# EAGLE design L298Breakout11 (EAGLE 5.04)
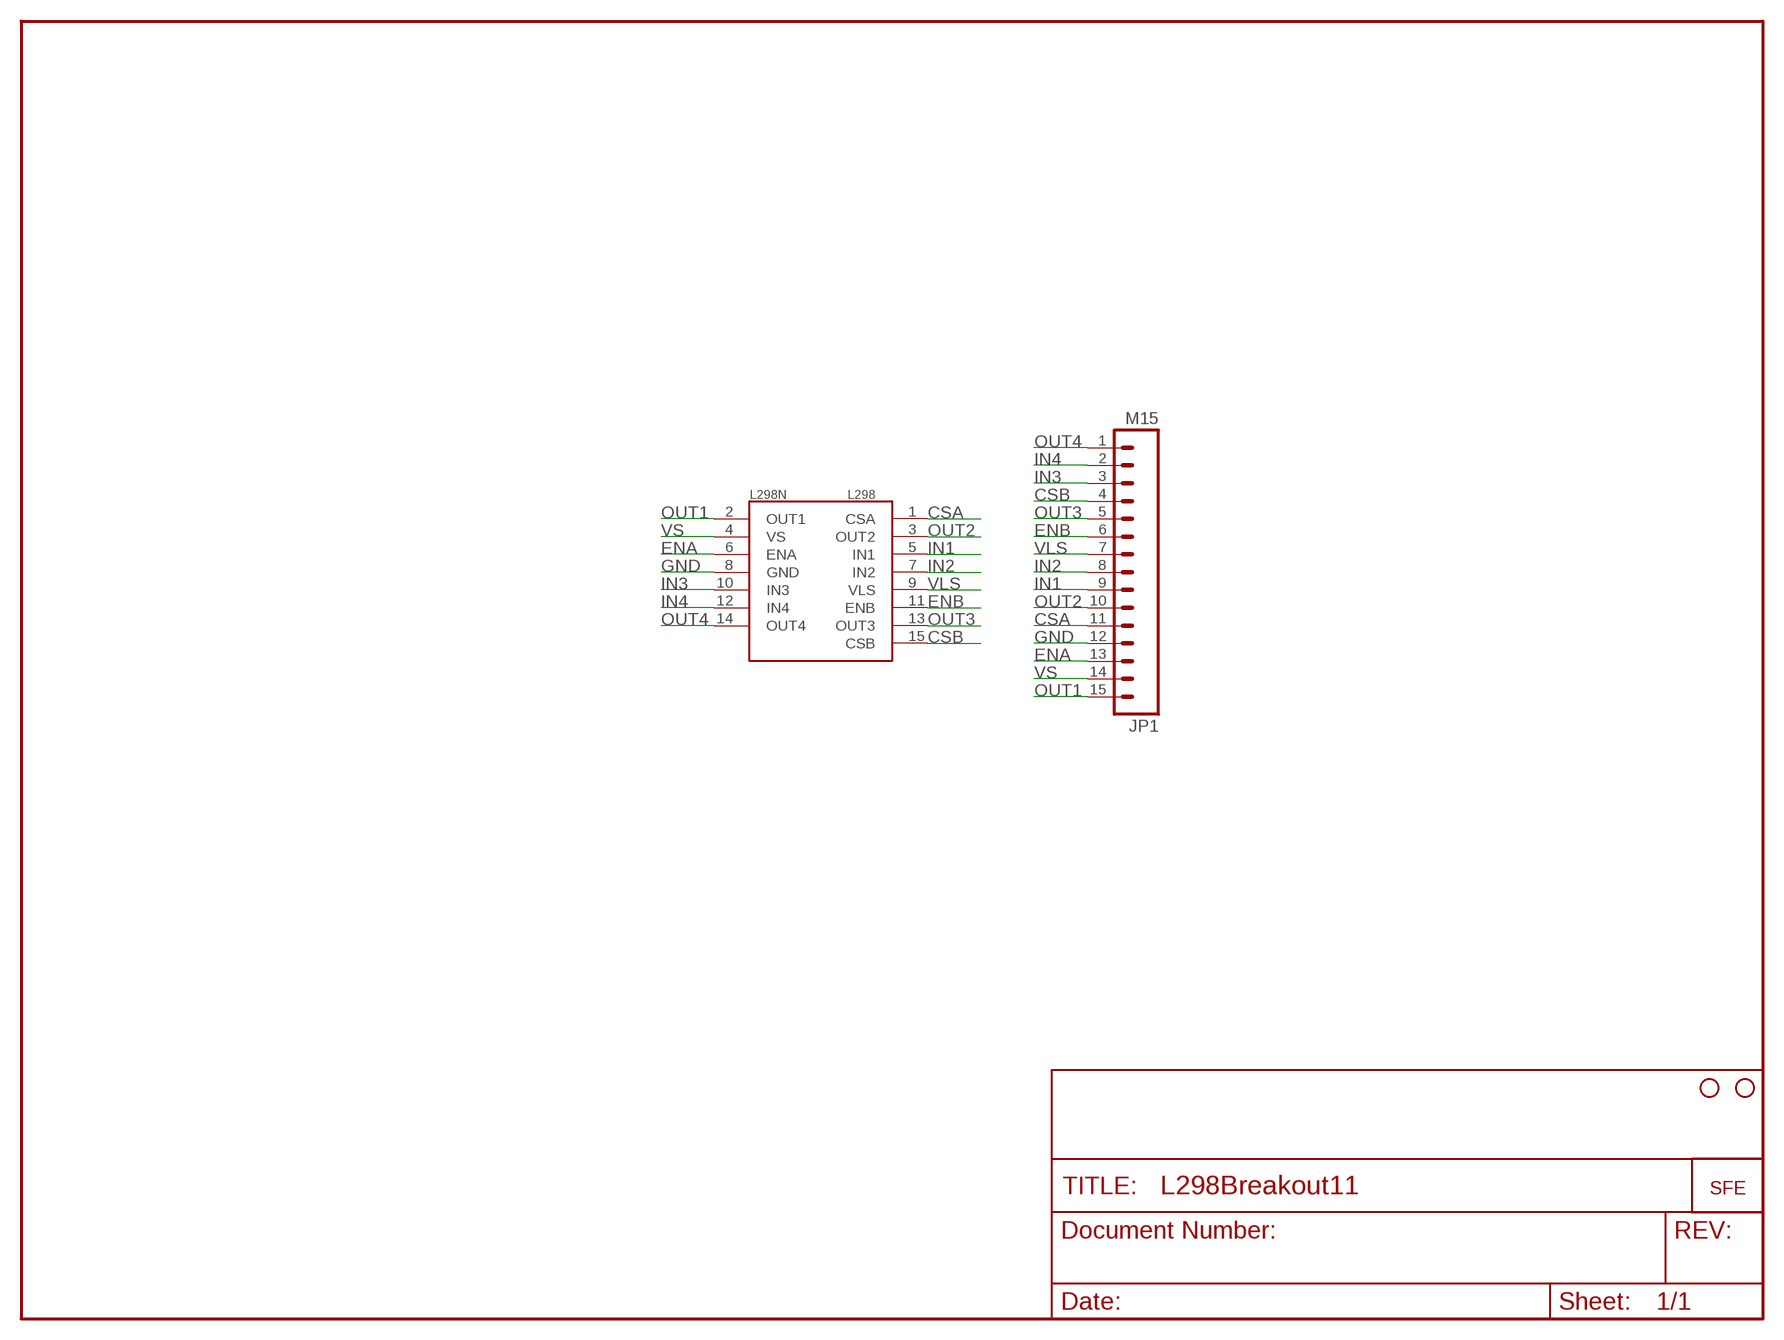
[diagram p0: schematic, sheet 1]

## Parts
JP1  M15  [1X15]
JP2  STAND-OFF  [STAND-OFF]
JP3  STAND-OFF  [STAND-OFF]
JP4  LOGO-SFENEW  [SFE-NEW-WEBLOGO]
L298N  L298  [MULTIWATT15]

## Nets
CSA: JP1.11 L298N.1(CSA)
CSB: JP1.4 L298N.15(CSB)
ENA: JP1.13 L298N.6(ENA)
ENB: JP1.6 L298N.11(ENB)
GND: JP1.12 L298N.8(GND)
IN1: JP1.9 L298N.5(IN1)
IN2: JP1.8 L298N.7(IN2)
IN3: JP1.3 L298N.10(IN3)
IN4: JP1.2 L298N.12(IN4)
OUT1: JP1.15 L298N.2(OUT1)
OUT2: JP1.10 L298N.3(OUT2)
OUT3: JP1.5 L298N.13(OUT3)
OUT4: JP1.1 L298N.14(OUT4)
VLS: JP1.7 L298N.9(VLS)
VS: JP1.14 L298N.4(VS)

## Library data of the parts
JP1 = SparkFun:M15: Header 15 Standard 15-pin 0.1" header. Use with straight break away headers (SKU : PRT-00116), right angle break away headers (PRT-00553), swiss pins (PRT-00743), machine pins (PRT-00117), and female headers (PRT-00115).
JP2 JP3 = SparkFun:STAND-OFF: Stand Off
JP4 = SparkFun:LOGO-SFE: Spark Fun Electronics PCB Logo
L298N = SparkFun:L298: L298 Dual Full Bridge Driver

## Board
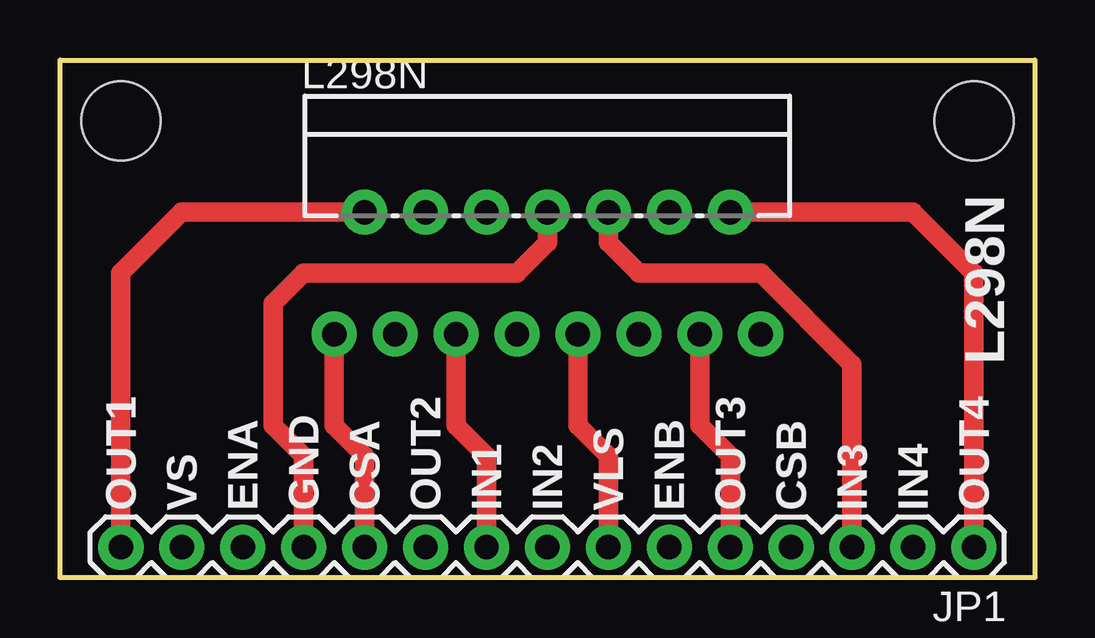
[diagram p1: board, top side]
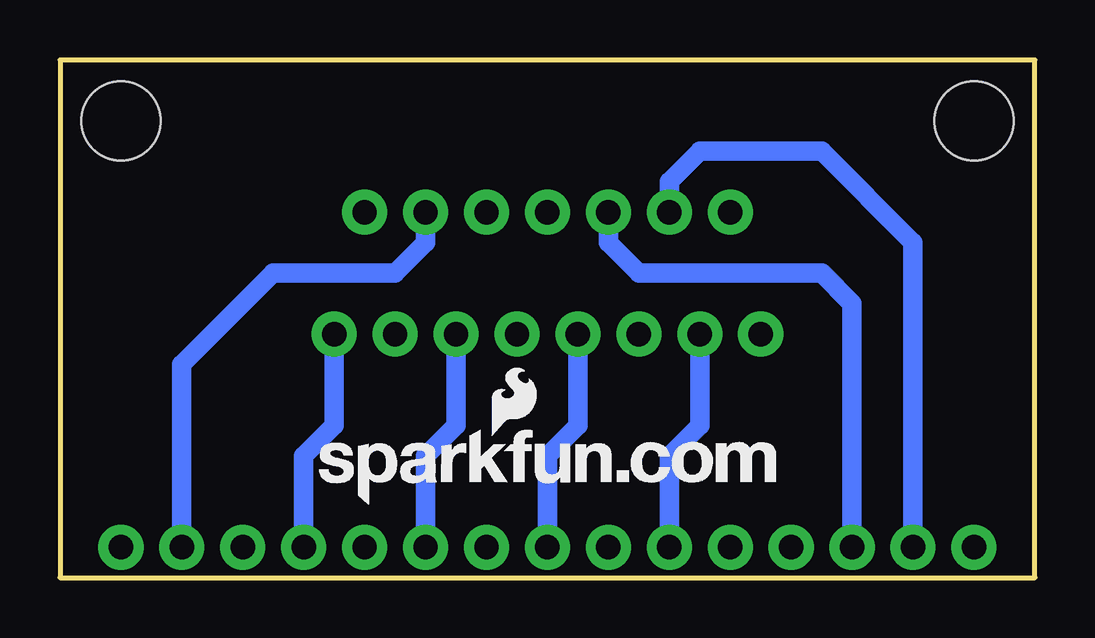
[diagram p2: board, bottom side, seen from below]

Size 40.64 x 21.59 mm. Coordinates in mm from the lower left corner, seen from the top.
Outline: 0,0 0,21.59 40.64,21.59 40.64,0 0,0
Copper layers (1*16): Top 0.035mm / dielectric 1.5mm / Bottom 0.035mm
Design rules "SparkFun": minimum track width 8mil, minimum drill 20mil, track to track 8mil, track to pad 8mil, pad to pad 8mil, via to via 8mil, smd to smd 8mil, copper to edge 9mil, drill to drill 8mil, minimum pad ring 12mil, minimum via ring 10mil, stop-mask expansion 4mil, vias tented up to drill 20mil, thermal gap 10mil

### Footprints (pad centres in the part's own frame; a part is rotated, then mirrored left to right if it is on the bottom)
1X15 = drill 1.016 pad 1.88 round: 1 0,0; 2 2.54,0; 3 5.08,0; 4 7.62,0; 5 10.16,0; 6 12.7,0; 7 15.24,0; 8 17.78,0; 9 20.32,0; 10 22.86,0; 11 25.4,0; 12 27.94,0; 13 30.48,0; 14 33.02,0; 15 35.56,0
STAND-OFF = hole 3.302: 0,0
MULTIWATT15 = drill 1.016 pad 1.88 round: 1 -8.89,-2.54; 2 -7.62,2.54; 3 -6.35,-2.54; 4 -5.08,2.54; 5 -3.81,-2.54; 6 -2.54,2.54; 7 -1.27,-2.54; 8 0,2.54; 9 1.27,-2.54; 10 2.54,2.54; 11 3.81,-2.54; 12 5.08,2.54; 13 6.35,-2.54; 14 7.62,2.54; 15 8.89,-2.54

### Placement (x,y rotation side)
JP1  38.1,1.27 180 top
JP2  2.54,19.05 0 top
JP3  38.1,19.05 0 top
JP4  29.84,3.05 0 bottom
L298N  20.32,12.7 0 top

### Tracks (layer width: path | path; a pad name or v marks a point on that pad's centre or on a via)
CSA
  Top 0.813: JP1.11 12.7,5.08 11.43,6.35 L298N.1
CSB
  Bottom 0.813: JP1.4 30.48,5.08 29.21,6.35 L298N.15
ENA
  Bottom 0.813: JP1.13 7.62,11.43 8.89,12.7 16.51,12.7 17.78,13.97 L298N.6
ENB
  Bottom 0.813: JP1.6 25.4,5.08 24.13,6.35 L298N.11
GND
  Top 0.813: JP1.12 10.16,5.08 8.89,6.35 8.89,11.43 10.16,12.7 19.05,12.7 20.32,13.97 L298N.8
IN1
  Top 0.813: JP1.9 17.78,5.08 16.51,6.35 L298N.5
IN2
  Bottom 0.813: JP1.8 20.32,5.08 19.05,6.35 L298N.7
IN3
  Top 0.813: JP1.3 33.02,8.89 29.21,12.7 24.13,12.7 22.86,13.97 L298N.10
IN4
  Bottom 0.813: JP1.2 35.56,8.89 31.75,12.7 26.67,12.7 25.4,13.97 L298N.12
OUT1
  Top 0.813: JP1.15 2.54,12.7 5.08,15.24 L298N.2
OUT2
  Bottom 0.813: JP1.10 15.24,5.08 13.97,6.35 L298N.3
OUT3
  Top 0.813: JP1.5 27.94,5.08 26.67,6.35 L298N.13
OUT4
  Top 0.813: JP1.1 38.1,12.7 35.56,15.24 L298N.14
VLS
  Top 0.813: JP1.7 22.86,5.08 21.59,6.35 L298N.9
VS
  Bottom 0.813: JP1.14 5.08,13.97 8.89,17.78 13.97,17.78 15.24,16.51 L298N.4

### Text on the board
tPlace: L298N | OUT1 | VS | ENA | GND | CSA | OUT2 | IN1 | IN2 | VLS | ENB | OUT3 | CSB | IN3 | IN4 | OUT4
